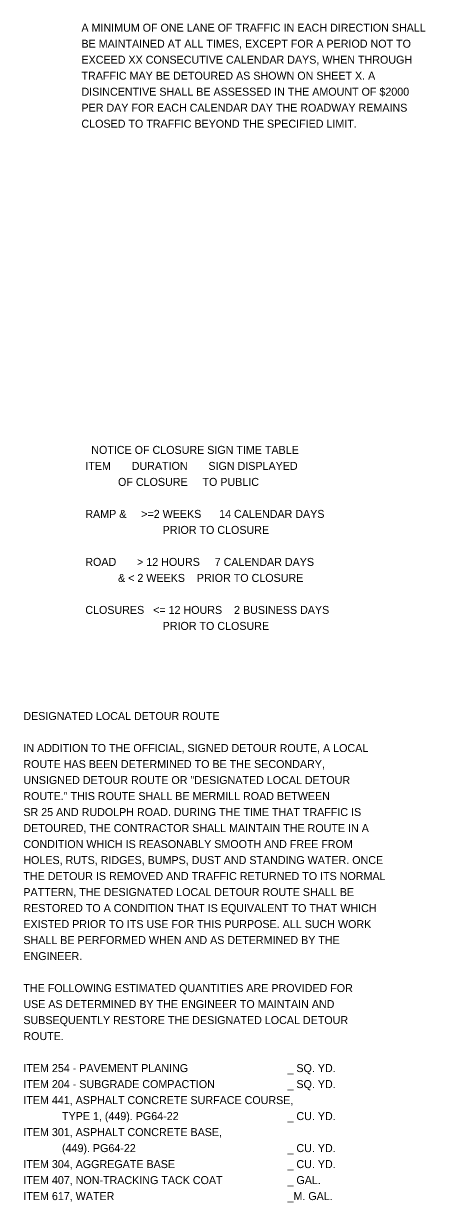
# Model space of a CAD drawing. Extents: x -7.7 to 42.4, y 0 to 36.3.
# Drawn here: x 35.39 to 42.42, y -0.05 to 20.58 of the extents above; entities that cross this region are included whole.
import ezdxf

# ---------------------------------------------------------------- set-up
doc = ezdxf.new("R2010")
doc.units = 0
doc.layers.add('SH_Text', color=7, linetype='Continuous')

msp = doc.modelspace()

# ---------------------------------------------------------------- texts
at = {"layer": 'SH_Text'}
for s, p in [('A MINIMUM OF ONE LANE OF TRAFFIC IN EACH DIRECTION SHALL', (36.4, 20.44)), ('BE MAINTAINED AT ALL TIMES, EXCEPT FOR A PERIOD NOT TO', (36.4, 20.16)), ('EXCEED XX CONSECUTIVE CALENDAR DAYS, WHEN THROUGH', (36.4, 19.88)), ('TRAFFIC MAY BE DETOURED AS SHOWN ON SHEET X. A', (36.4, 19.6)), ('DISINCENTIVE SHALL BE ASSESSED IN THE AMOUNT OF $2000', (36.4, 19.32)), ('PER DAY FOR EACH CALENDAR DAY THE ROADWAY REMAINS', (36.4, 19.04)), ('CLOSED TO TRAFFIC BEYOND THE SPECIFIED LIMIT.', (36.4, 18.76)), ('  NOTICE OF CLOSURE SIGN TIME TABLE', (36.468, 13.052)), ('ITEM       DURATION       SIGN DISPLAYED', (36.468, 12.772)), ('           OF CLOSURE     TO PUBLIC', (36.468, 12.492)), ('RAMP &     >=2 WEEKS      14 CALENDAR DAYS', (36.468, 11.932)), ('                          PRIOR TO CLOSURE', (36.468, 11.652)), ('ROAD       > 12 HOURS     7 CALENDAR DAYS', (36.468, 11.092)), ('           & < 2 WEEKS    PRIOR TO CLOSURE', (36.468, 10.812)), ('CLOSURES   <= 12 HOURS    2 BUSINESS DAYS', (36.468, 10.252)), ('                          PRIOR TO CLOSURE', (36.468, 9.972)), ('DESIGNATED LOCAL DETOUR ROUTE', (35.384, 8.395)), ('IN ADDITION TO THE OFFICIAL, SIGNED DETOUR ROUTE, A LOCAL', (35.384, 7.835)), ('ROUTE HAS BEEN DETERMINED TO BE THE SECONDARY,', (35.384, 7.555)), ('UNSIGNED DETOUR ROUTE OR "DESIGNATED LOCAL DETOUR', (35.384, 7.275)), ('ROUTE." THIS ROUTE SHALL BE MERMILL ROAD BETWEEN', (35.384, 6.995)), ('SR 25 AND RUDOLPH ROAD. DURING THE TIME THAT TRAFFIC IS', (35.384, 6.715)), ('DETOURED, THE CONTRACTOR SHALL MAINTAIN THE ROUTE IN A', (35.384, 6.435)), ('CONDITION WHICH IS REASONABLY SMOOTH AND FREE FROM', (35.384, 6.155)), ('HOLES, RUTS, RIDGES, BUMPS, DUST AND STANDING WATER. ONCE', (35.384, 5.875)), ('THE DETOUR IS REMOVED AND TRAFFIC RETURNED TO ITS NORMAL', (35.384, 5.595)), ('PATTERN, THE DESIGNATED LOCAL DETOUR ROUTE SHALL BE', (35.384, 5.315)), ('RESTORED TO A CONDITION THAT IS EQUIVALENT TO THAT WHICH', (35.384, 5.035)), ('EXISTED PRIOR TO ITS USE FOR THIS PURPOSE. ALL SUCH WORK', (35.384, 4.755)), ('SHALL BE PERFORMED WHEN AND AS DETERMINED BY THE', (35.384, 4.475)), ('ENGINEER.', (35.384, 4.195)), ('THE FOLLOWING ESTIMATED QUANTITIES ARE PROVIDED FOR', (35.384, 3.635)), ('USE AS DETERMINED BY THE ENGINEER TO MAINTAIN AND', (35.384, 3.355)), ('SUBSEQUENTLY RESTORE THE DESIGNATED LOCAL DETOUR', (35.384, 3.075)), ('ROUTE.', (35.384, 2.795)), ('ITEM 254 - PAVEMENT PLANING', (35.384, 2.235)), ('_ SQ. YD.', (40.004, 2.235)), ('ITEM 204 - SUBGRADE COMPACTION', (35.384, 1.955)), ('_ SQ. YD.', (40.004, 1.955)), ('ITEM 441, ASPHALT CONCRETE SURFACE COURSE,', (35.384, 1.675)), ('             TYPE 1, (449). PG64-22', (35.384, 1.395)), ('_ CU. YD.', (40.004, 1.395)), ('ITEM 301, ASPHALT CONCRETE BASE,', (35.384, 1.115)), ('             (449). PG64-22', (35.384, 0.835)), ('_ CU. YD.', (40.004, 0.835)), ('ITEM 304, AGGREGATE BASE', (35.384, 0.555)), ('_ CU. YD.', (40.004, 0.555)), ('ITEM 407, NON-TRACKING TACK COAT', (35.384, 0.275)), ('_ GAL.', (40.004, 0.275)), ('ITEM 617, WATER', (35.384, -0.005)), ('_M. GAL.', (40.004, -0.005))]:
    msp.add_text(s, height=0.14, dxfattribs=at).set_placement(p)

doc.saveas('drawing.dxf')
